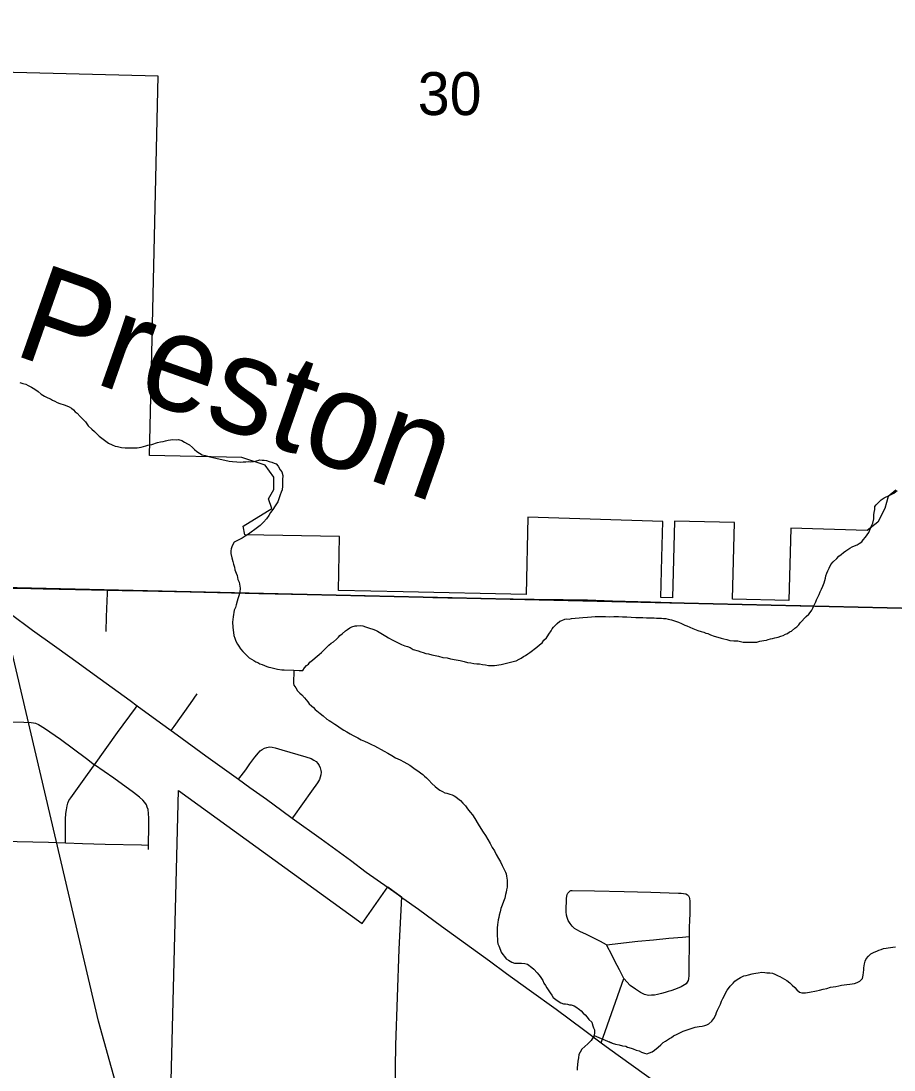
# Model space of a CAD drawing. Extents: x 0 to 34, y 0 to 22.
# Drawn here: x 7.471 to 8.323, y 16.904 to 17.928 of the extents above; entities that cross this region are included whole.
import ezdxf

# ---------------------------------------------------------------- set-up
doc = ezdxf.new("R2010")
doc.units = 0
for name, color, linetype in [('Default', 7, 'Continuous'), ('GM_X_City_Street', 7, 'Continuous'), ('GM_X_County_Road', 7, 'Continuous'), ('GM_X_Minor_River', 7, 'Continuous'), ('GM_X_Minor_River_Text', 7, 'Continuous'), ('GM_X_Rail_Line', 7, 'Continuous'), ('GM_X_Section', 7, 'Continuous'), ('GM_X_Section_Text', 7, 'Continuous')]:
    doc.layers.add(name, color=color, linetype=linetype)

msp = doc.modelspace()

# ---------------------------------------------------------------- linework, layer by layer
at = {"layer": 'Default'}
for points in [[(8.3248, 17.47), (8.3172, 17.4641), (8.3139, 17.4523), (8.3071, 17.4388), (8.2969, 17.4307), (8.2224, 17.4329), (8.2204, 17.3624), (8.1654, 17.3637), (8.1673, 17.4387), (8.1379, 17.4393), (8.1086, 17.44), (8.1067, 17.365), (8.0953, 17.3653), (8.0963, 17.4044), (8.0972, 17.4396), (7.9655, 17.4439), (7.9638, 17.3683), (7.8439, 17.3711), (7.7808, 17.3722), (7.7816, 17.4248), (7.6892, 17.4264), (7.6876, 17.4349), (7.7158, 17.4523), (7.7124, 17.4616), (7.7175, 17.4708), (7.7175, 17.4827), (7.709, 17.4945), (7.6863, 17.5021), (7.5961, 17.5038), (7.6046, 17.8742), (7.4249, 17.8786)], [(7.6168, 16.8685), (7.6244, 17.1771), (7.8038, 17.0472), (7.8289, 17.0831), (7.8424, 17.0734), (7.8398, 17.0223), (7.8365, 16.9285), (7.8354, 16.8636)]]:
    msp.add_lwpolyline(points, dxfattribs=at)
at = {"layer": 'GM_X_City_Street'}
for points in [[(7.5538, 17.3321), (7.5544, 17.3467), (7.5548, 17.3623), (7.5551, 17.3694), (7.5552, 17.3727)], [(7.6175, 17.2355), (7.6203, 17.2395), (7.6363, 17.262), (7.6427, 17.2713)], [(7.5141, 17.1261), (7.5141, 17.1318), (7.5143, 17.1492), (7.5146, 17.1547), (7.5152, 17.1583), (7.516, 17.1623), (7.5166, 17.1649), (7.5176, 17.1674), (7.5193, 17.17), (7.5293, 17.1837), (7.5358, 17.1928), (7.5426, 17.2022), (7.5651, 17.2337), (7.5825, 17.2575), (7.5842, 17.2598)], [(7.4575, 17.244), (7.4737, 17.2439), (7.4806, 17.2435), (7.4831, 17.2432), (7.4851, 17.2427), (7.488, 17.2414), (7.4939, 17.2378), (7.5093, 17.2272), (7.5348, 17.2083), (7.5426, 17.2022)], [(7.6832, 17.1881), (7.6858, 17.1914), (7.6904, 17.1973), (7.6943, 17.203), (7.699, 17.2096), (7.7025, 17.214), (7.7043, 17.2157), (7.7062, 17.2172), (7.7084, 17.2185), (7.7107, 17.2192), (7.7133, 17.2197), (7.7159, 17.2194), (7.7188, 17.2187), (7.7254, 17.2168), (7.7487, 17.2101), (7.754, 17.2082), (7.7568, 17.2067), (7.7588, 17.2053), (7.7605, 17.2035), (7.7619, 17.2014), (7.7629, 17.1991), (7.7636, 17.1967), (7.7638, 17.1949), (7.7636, 17.1924), (7.763, 17.19), (7.7621, 17.1877), (7.7602, 17.1845), (7.7543, 17.1764), (7.7367, 17.1517), (7.7355, 17.1502)], [(7.5953, 17.1194), (7.5953, 17.1238), (7.5955, 17.1422), (7.5955, 17.1501), (7.5953, 17.1548), (7.5948, 17.1585), (7.5941, 17.1609), (7.5932, 17.1632), (7.5918, 17.1653), (7.5898, 17.1677), (7.5866, 17.1706), (7.5807, 17.1752), (7.5615, 17.189), (7.5426, 17.2022)], [(7.4373, 17.1283), (7.4423, 17.1281), (7.4672, 17.1275), (7.4977, 17.1266), (7.5141, 17.1261), (7.5307, 17.1255), (7.5531, 17.1248), (7.5885, 17.124), (7.5953, 17.1238)], [(8.0373, 16.9309), (8.0594, 16.9936), (8.055, 17.0021), (8.0505, 17.0107), (8.0478, 17.0161), (8.0423, 17.0266), (8.0366, 17.0298), (8.0294, 17.0334), (8.0221, 17.0369), (8.0171, 17.0393), (8.0133, 17.0413), (8.0112, 17.0426), (8.0089, 17.0447), (8.007, 17.0472), (8.0051, 17.0504), (8.0039, 17.0532), (8.0032, 17.0556), (8.0029, 17.0586), (8.0029, 17.0635), (8.0032, 17.068), (8.0033, 17.0716), (8.0036, 17.074), (8.004, 17.0757), (8.0046, 17.0769), (8.0052, 17.0777), (8.006, 17.0784), (8.0068, 17.0791), (8.0077, 17.0795), (8.0087, 17.0796), (8.0308, 17.0793), (8.0596, 17.0785), (8.0855, 17.0778), (8.1125, 17.0771), (8.1152, 17.077), (8.1176, 17.0767), (8.1197, 17.0762), (8.1215, 17.0753), (8.1225, 17.0743), (8.1231, 17.0731), (8.1234, 17.0716), (8.1236, 17.0692), (8.1237, 17.065), (8.1236, 17.0566), (8.1235, 17.0508), (8.1232, 17.0431), (8.1231, 17.0379), (8.123, 17.0346), (8.1231, 17.03), (8.1229, 17.0226), (8.1228, 17.0108), (8.1228, 17.004), (8.1228, 16.9965), (8.1225, 16.9934), (8.122, 16.9916), (8.1212, 16.99), (8.12, 16.9886), (8.1185, 16.9874), (8.1152, 16.9856), (8.1098, 16.9832), (8.105, 16.9818), (8.1024, 16.981), (8.0996, 16.9801), (8.0961, 16.9792), (8.0923, 16.9781), (8.0893, 16.9775), (8.0863, 16.9773), (8.0832, 16.9772), (8.0794, 16.9781), (8.0757, 16.9801), (8.0707, 16.9833), (8.0655, 16.987), (8.0594, 16.9936)], [(8.0423, 17.0266), (8.0729, 17.0302), (8.0881, 17.0315), (8.1031, 17.033), (8.1167, 17.0341), (8.123, 17.0346)]]:
    msp.add_lwpolyline(points, dxfattribs=at)
at = {"layer": 'GM_X_County_Road'}
msp.add_line((8.0373, 16.9309), (8.0456, 16.9248), dxfattribs=at)
for points in [[(7.4258, 17.3747), (7.4379, 17.3658), (7.4602, 17.3499), (7.4821, 17.3335), (7.5034, 17.3184), (7.5186, 17.3076), (7.5301, 17.299), (7.5421, 17.2902), (7.5774, 17.2648), (7.5842, 17.2598)], [(7.4258, 17.3747), (7.4499, 17.3746), (7.4679, 17.3745), (7.4926, 17.374), (7.5552, 17.3727)], [(7.5552, 17.3727), (7.5648, 17.3725), (7.5695, 17.3724)], [(7.5695, 17.3724), (7.574, 17.3723), (7.6359, 17.371), (7.7031, 17.3694), (7.7664, 17.3679), (7.806, 17.367), (7.8447, 17.3664)], [(7.8447, 17.3664), (7.8727, 17.3655), (7.8876, 17.3651), (7.9062, 17.3648), (7.9196, 17.3646), (7.9512, 17.3641), (7.9716, 17.3637), (8.0002, 17.3634), (8.0239, 17.363), (8.0482, 17.3621), (8.0854, 17.3612), (8.1469, 17.3593), (8.232, 17.3575), (8.2793, 17.3563), (8.3331, 17.355), (8.3469, 17.3547)], [(7.5842, 17.2598), (7.6071, 17.2432), (7.6175, 17.2355)], [(7.6175, 17.2355), (7.6231, 17.2314), (7.6514, 17.2111), (7.6832, 17.1881)], [(7.6832, 17.1881), (7.6942, 17.1801), (7.7103, 17.1685), (7.7254, 17.1575), (7.7355, 17.1502)], [(7.7355, 17.1502), (7.7637, 17.1298), (7.7923, 17.109), (7.8079, 17.0976), (7.8292, 17.0825)], [(7.8292, 17.0825), (7.8394, 17.0752), (7.8427, 17.0728), (7.8435, 17.0722)], [(7.8435, 17.0722), (7.8588, 17.0612), (7.8813, 17.0446), (7.9283, 17.0108), (7.9449, 16.9987), (7.967, 16.9826), (7.9933, 16.9638), (8.0198, 16.9441), (8.0373, 16.9309)], [(8.0456, 16.9248), (8.0897, 16.8932), (8.1089, 16.8784), (8.1278, 16.8643), (8.1484, 16.8492), (8.1625, 16.839), (8.1776, 16.8281), (8.1938, 16.8163)]]:
    msp.add_lwpolyline(points, dxfattribs=at)
at = {"layer": 'GM_X_Minor_River'}
for points in [[(7.4696, 17.5751), (7.4726, 17.5743), (7.4756, 17.5734), (7.4778, 17.5722), (7.4812, 17.5706), (7.4842, 17.5686), (7.4875, 17.5663), (7.4905, 17.5639), (7.4939, 17.5619), (7.4969, 17.5603), (7.4995, 17.5591), (7.5017, 17.5579), (7.504, 17.557), (7.5062, 17.5558), (7.5088, 17.5546), (7.513, 17.5534), (7.5156, 17.5525), (7.5179, 17.5513), (7.5201, 17.5501), (7.522, 17.5485), (7.5238, 17.5466), (7.5257, 17.5454), (7.5286, 17.5419), (7.5312, 17.5395), (7.5338, 17.5368), (7.5363, 17.5329), (7.54, 17.5298), (7.5426, 17.5274), (7.5448, 17.5251), (7.547, 17.5227), (7.5563, 17.516), (7.5597, 17.5144), (7.5627, 17.5131), (7.565, 17.5127), (7.5688, 17.5118), (7.5725, 17.5113), (7.5752, 17.5113), (7.5779, 17.5116), (7.5809, 17.5115), (7.5843, 17.5114), (7.5862, 17.5117), (7.5881, 17.512), (7.5904, 17.5127), (7.5927, 17.5134), (7.5947, 17.5141), (7.5985, 17.5148), (7.6042, 17.5165), (7.6069, 17.5172)], [(7.6069, 17.5172), (7.6096, 17.5175), (7.6119, 17.5182), (7.6145, 17.5189), (7.6191, 17.5195), (7.6222, 17.5194), (7.6244, 17.5197), (7.6278, 17.5185), (7.6304, 17.5169), (7.6334, 17.5153), (7.6353, 17.5145), (7.6383, 17.5117), (7.6401, 17.5098), (7.6423, 17.5078), (7.6449, 17.5062), (7.6476, 17.5046), (7.6506, 17.5041), (7.6528, 17.5033), (7.6551, 17.5025), (7.6581, 17.502), (7.6611, 17.5015), (7.674, 17.4985), (7.6774, 17.498), (7.6815, 17.4979), (7.685, 17.4974), (7.6876, 17.4977), (7.6903, 17.4977), (7.6933, 17.498), (7.6952, 17.4979), (7.6979, 17.4982), (7.6998, 17.4985), (7.704, 17.4996), (7.7063, 17.4995), (7.7082, 17.4994), (7.7104, 17.499), (7.7131, 17.4982), (7.7157, 17.4973), (7.718, 17.4965), (7.7198, 17.4957), (7.7217, 17.4937), (7.7239, 17.4899), (7.7253, 17.4879), (7.7264, 17.4845), (7.7262, 17.4803), (7.7262, 17.4776), (7.7261, 17.4742), (7.7256, 17.4704), (7.7247, 17.4682), (7.7239, 17.4655), (7.7227, 17.4625), (7.7214, 17.4587), (7.719, 17.455), (7.7167, 17.4513), (7.7143, 17.4483), (7.7127, 17.4453), (7.7103, 17.4423), (7.7076, 17.439), (7.7044, 17.4357), (7.699, 17.4316), (7.6955, 17.4291), (7.6928, 17.4273), (7.6897, 17.4251), (7.6866, 17.4233), (7.6789, 17.4193), (7.6769, 17.4159), (7.676, 17.4129), (7.6756, 17.411), (7.6755, 17.4084), (7.6766, 17.4041), (7.6776, 17.4007), (7.6783, 17.398), (7.6793, 17.3949), (7.6796, 17.3923), (7.6807, 17.3892), (7.6817, 17.3869), (7.6824, 17.3831), (7.6838, 17.3804), (7.6842, 17.3785), (7.6848, 17.3746), (7.6843, 17.3705), (7.6835, 17.3671), (7.6826, 17.3641), (7.6818, 17.3618), (7.6809, 17.3584), (7.6801, 17.3558), (7.6789, 17.3531), (7.6779, 17.3467), (7.6774, 17.3414), (7.6776, 17.3364), (7.6785, 17.3284), (7.6796, 17.3257), (7.6806, 17.3227), (7.6821, 17.32), (7.6835, 17.318), (7.685, 17.3153), (7.6872, 17.3126), (7.6913, 17.3087), (7.6935, 17.3067), (7.6957, 17.3051), (7.698, 17.3039), (7.7002, 17.3027)], [(8.2547, 17.3798), (8.2555, 17.3821), (8.256, 17.3844), (8.2564, 17.3866), (8.2573, 17.3893), (8.2585, 17.3915), (8.2597, 17.3941), (8.2613, 17.3975), (8.2637, 17.4001), (8.2672, 17.4034), (8.2691, 17.4056), (8.2715, 17.4075), (8.2738, 17.4093), (8.2761, 17.4111), (8.2781, 17.4122), (8.28, 17.4137), (8.2823, 17.4148), (8.2846, 17.4158), (8.2869, 17.4169), (8.2889, 17.418), (8.2916, 17.4198), (8.2928, 17.4217), (8.2951, 17.4243), (8.2983, 17.4288), (8.3011, 17.4355), (8.3024, 17.4381), (8.3032, 17.4423), (8.3034, 17.4461), (8.3038, 17.4484), (8.3043, 17.4514), (8.3043, 17.4541), (8.3055, 17.4559), (8.3083, 17.4585), (8.3106, 17.4607), (8.3133, 17.4625), (8.3153, 17.4636), (8.3179, 17.4647), (8.3203, 17.4658), (8.323, 17.4672), (8.3261, 17.4698)], [(7.9862, 17.3298), (7.9882, 17.3328), (7.9894, 17.3347), (7.9906, 17.3365), (7.9926, 17.3384), (7.9941, 17.3402), (7.9969, 17.3424), (7.9988, 17.3431), (8.0018, 17.3442), (8.0038, 17.3445), (8.006, 17.3444), (8.0083, 17.3448), (8.0118, 17.3454), (8.0156, 17.3457), (8.0194, 17.346), (8.0239, 17.3462), (8.0277, 17.3465), (8.0312, 17.3468), (8.0369, 17.347), (8.0414, 17.3468), (8.0456, 17.3467), (8.0494, 17.347), (8.054, 17.3469), (8.0581, 17.3467), (8.0623, 17.3466), (8.0665, 17.3461), (8.071, 17.346), (8.0744, 17.3459), (8.0779, 17.3458), (8.0813, 17.3457), (8.0839, 17.3456), (8.0862, 17.3455), (8.0889, 17.3455), (8.0911, 17.3454), (8.0938, 17.3453), (8.0961, 17.3453), (8.098, 17.3448), (8.1002, 17.3448), (8.1025, 17.3443), (8.1059, 17.3435), (8.1127, 17.3414), (8.1157, 17.3401), (8.1187, 17.3385), (8.1209, 17.3377), (8.1236, 17.3365), (8.1266, 17.3353), (8.1314, 17.3332), (8.1348, 17.3324), (8.1375, 17.3315), (8.1393, 17.3307), (8.1412, 17.3303), (8.1438, 17.3291), (8.1476, 17.3278), (8.151, 17.3266), (8.1544, 17.3257), (8.157, 17.3252), (8.1597, 17.3244), (8.1627, 17.3236), (8.1668, 17.3231), (8.1687, 17.323), (8.1706, 17.323), (8.1733, 17.3225), (8.1759, 17.322), (8.1786, 17.322), (8.1812, 17.3219), (8.1839, 17.3218), (8.1866, 17.3217), (8.1892, 17.322), (8.1919, 17.3227), (8.1961, 17.3234), (8.1984, 17.3237), (8.2003, 17.3244), (8.2026, 17.3251), (8.2045, 17.3254), (8.2068, 17.3261), (8.2099, 17.3268), (8.2126, 17.3278), (8.2149, 17.3285), (8.2172, 17.3296), (8.2191, 17.3303), (8.221, 17.3318), (8.2229, 17.3325), (8.2261, 17.3354), (8.228, 17.3369), (8.23, 17.3387), (8.2315, 17.3406), (8.2374, 17.3469), (8.2398, 17.3491), (8.2413, 17.3509), (8.2429, 17.3532), (8.2437, 17.3551), (8.2449, 17.3573), (8.2458, 17.3592), (8.2466, 17.3611), (8.2474, 17.3633), (8.2486, 17.3656), (8.2498, 17.3682), (8.251, 17.3708), (8.2522, 17.3734), (8.2535, 17.3764), (8.2547, 17.3798)], [(7.7002, 17.3027), (7.7021, 17.3019), (7.7039, 17.3007), (7.7062, 17.2999), (7.7084, 17.299), (7.7107, 17.2982), (7.7126, 17.2974), (7.7148, 17.297), (7.7213, 17.2956), (7.7254, 17.2948), (7.7277, 17.2947), (7.7372, 17.2944), (7.7425, 17.2943), (7.7459, 17.2942), (7.7475, 17.2968), (7.7495, 17.299), (7.7514, 17.3005), (7.7526, 17.3023), (7.7553, 17.3042), (7.758, 17.3067), (7.76, 17.3082), (7.7619, 17.3097), (7.7643, 17.3119), (7.7662, 17.3137), (7.7686, 17.3163), (7.7713, 17.3189), (7.7736, 17.3207), (7.776, 17.3222), (7.7787, 17.3248), (7.7807, 17.3266), (7.7822, 17.3285), (7.7842, 17.3299), (7.7877, 17.3329), (7.7896, 17.3343), (7.7919, 17.3358), (7.7939, 17.3369), (7.7969, 17.3379), (7.7988, 17.3379), (7.8023, 17.3382), (7.8045, 17.3377), (7.8072, 17.3369), (7.8109, 17.3356), (7.8143, 17.3344), (7.8169, 17.3336), (7.8188, 17.3327), (7.827, 17.3276), (7.8296, 17.326), (7.833, 17.324), (7.8364, 17.3224), (7.839, 17.3211), (7.8424, 17.3195), (7.8454, 17.3183), (7.848, 17.3175), (7.8506, 17.3166), (7.8536, 17.3146), (7.8585, 17.3133), (7.8612, 17.3125), (7.8634, 17.3117), (7.866, 17.3108), (7.8687, 17.3104), (7.8717, 17.3095), (7.8751, 17.3087), (7.8785, 17.3082), (7.8826, 17.3069), (7.8868, 17.3064), (7.8902, 17.3056), (7.8955, 17.3047), (7.8996, 17.3038), (7.9034, 17.3029), (7.9068, 17.3021), (7.9098, 17.3016), (7.9129, 17.3011), (7.9159, 17.3007), (7.9185, 17.3006), (7.9212, 17.3001), (7.9242, 17.2997), (7.9272, 17.2992), (7.9299, 17.2991), (7.9329, 17.299), (7.9352, 17.2993), (7.9371, 17.2997), (7.9394, 17.3), (7.9421, 17.3007), (7.9448, 17.3014), (7.9474, 17.302), (7.9501, 17.3027), (7.9524, 17.3034), (7.9543, 17.3037), (7.957, 17.3052), (7.959, 17.3063), (7.9613, 17.3077), (7.9632, 17.3088), (7.9655, 17.3103), (7.9675, 17.3117), (7.9745, 17.3168), (7.9768, 17.3191), (7.9795, 17.3213), (7.9811, 17.3239), (7.9838, 17.3261), (7.985, 17.3279), (7.9862, 17.3298)], [(7.7372, 17.2944), (7.7368, 17.2815), (7.7371, 17.28), (7.739, 17.2773), (7.7408, 17.2745), (7.743, 17.2722), (7.7448, 17.2706), (7.7474, 17.2675), (7.7507, 17.2636), (7.7522, 17.2617), (7.7544, 17.2597), (7.7563, 17.2581), (7.7581, 17.2562), (7.7611, 17.2534), (7.7629, 17.2522), (7.7659, 17.2499), (7.7692, 17.2467), (7.7715, 17.2455), (7.7733, 17.2443), (7.7752, 17.2431), (7.7771, 17.2419), (7.7789, 17.2407), (7.7812, 17.2392), (7.7834, 17.2376), (7.786, 17.236), (7.789, 17.2344), (7.792, 17.2324), (7.795, 17.2308), (7.7995, 17.2284), (7.8028, 17.2267), (7.8062, 17.2251), (7.8096, 17.2235), (7.8129, 17.2219), (7.8159, 17.2207), (7.8253, 17.2154), (7.829, 17.2134), (7.8328, 17.2114), (7.8365, 17.209), (7.841, 17.207), (7.8444, 17.205), (7.8473, 17.2034), (7.8503, 17.2018), (7.8529, 17.1998), (7.8555, 17.1978), (7.8582, 17.1963), (7.8608, 17.1943), (7.863, 17.1927), (7.8648, 17.1911), (7.8667, 17.1895), (7.8689, 17.1872), (7.8719, 17.1841), (7.8752, 17.1809), (7.877, 17.1794), (7.8796, 17.1774), (7.8823, 17.1762), (7.8845, 17.175), (7.8864, 17.1745), (7.8894, 17.1737), (7.8917, 17.1728), (7.8935, 17.172), (7.8954, 17.1708), (7.8973, 17.1693), (7.8999, 17.1673), (7.9021, 17.1646), (7.9046, 17.1622), (7.9068, 17.1591), (7.9094, 17.156), (7.9116, 17.1533), (7.9138, 17.1498), (7.917, 17.1444), (7.9196, 17.1401), (7.9221, 17.1366), (7.9243, 17.1331), (7.9265, 17.1293), (7.9287, 17.1254), (7.9308, 17.1215), (7.933, 17.1184), (7.9348, 17.1146), (7.937, 17.1107), (7.9388, 17.1076), (7.9406, 17.1041), (7.9438, 17.0976), (7.9445, 17.0957), (7.9448, 17.0934), (7.9451, 17.0915), (7.9455, 17.0895), (7.9454, 17.0873), (7.9453, 17.085), (7.9453, 17.0827), (7.9448, 17.0801), (7.9444, 17.0778), (7.9439, 17.0755), (7.9431, 17.0721), (7.9418, 17.0687), (7.9406, 17.0654), (7.9393, 17.062), (7.9385, 17.0589), (7.9376, 17.0556), (7.9372, 17.0533), (7.9367, 17.051), (7.9363, 17.0484)], [(7.9363, 17.0484), (7.9359, 17.0465), (7.9357, 17.0427), (7.9357, 17.04), (7.9356, 17.0377), (7.9355, 17.0351), (7.9358, 17.0324), (7.9361, 17.0297), (7.9364, 17.0275), (7.9371, 17.0255), (7.9389, 17.0213), (7.9396, 17.0194), (7.9411, 17.0171), (7.9429, 17.0151), (7.9444, 17.0128), (7.9466, 17.0116), (7.95, 17.0096), (7.9526, 17.0087), (7.9553, 17.0087), (7.9575, 17.0086), (7.9594, 17.0085), (7.9625, 17.0084), (7.9651, 17.0076), (7.9696, 17.0044), (7.9714, 17.0029), (7.9748, 16.9993), (7.9762, 16.9974), (7.9777, 16.9955), (7.9802, 16.9916), (7.9813, 16.9893), (7.9827, 16.9869), (7.9842, 16.9846), (7.9853, 16.9827), (7.9875, 16.9796), (7.9889, 16.9773), (7.9904, 16.9753), (7.993, 16.9733), (7.996, 16.971), (7.9978, 16.9698), (8.0005, 16.9689), (8.0024, 16.9689), (8.0042, 16.9685), (8.0061, 16.968), (8.008, 16.968), (8.0107, 16.9671), (8.0125, 16.9659), (8.0159, 16.9636), (8.0177, 16.962), (8.0196, 16.96), (8.0214, 16.9581), (8.0236, 16.9561), (8.0251, 16.9538), (8.028, 16.951), (8.0291, 16.9476), (8.0298, 16.9457), (8.0305, 16.9437), (8.0308, 16.9411), (8.0303, 16.938), (8.0275, 16.9332), (8.024, 16.9299), (8.0213, 16.9273), (8.0182, 16.9247), (8.0166, 16.9217), (8.0154, 16.9195), (8.0149, 16.9164), (8.0144, 16.913), (8.0139, 16.9096), (8.0138, 16.9066), (8.0138, 16.9043)], [(8.293, 16.997), (8.2931, 16.9996), (8.2935, 17.0023), (8.2936, 17.0042), (8.294, 17.0061), (8.2941, 17.008), (8.2949, 17.0106), (8.2957, 17.0129), (8.2981, 17.0155), (8.3004, 17.0177), (8.3035, 17.0195), (8.3062, 17.0205), (8.3081, 17.0213), (8.3104, 17.0219), (8.3127, 17.023), (8.3154, 17.0233), (8.3173, 17.0236), (8.3196, 17.024), (8.3219, 17.0243), (8.3245, 17.0246)], [(8.0303, 16.938), (8.048, 16.9307), (8.045, 16.9319), (8.048, 16.9307), (8.0513, 16.9295), (8.0548, 16.929), (8.0581, 16.9281), (8.0612, 16.9276), (8.063, 16.9268), (8.0664, 16.9256), (8.0683, 16.9252), (8.0713, 16.9239), (8.0743, 16.9231), (8.0766, 16.9219), (8.0796, 16.921), (8.0818, 16.9202), (8.0868, 16.9223), (8.0892, 16.9238), (8.0927, 16.9267), (8.0954, 16.9289), (8.0977, 16.9312), (8.1001, 16.9326), (8.102, 16.9337), (8.1039, 16.9352), (8.1059, 16.9362), (8.1078, 16.9377), (8.1113, 16.9395), (8.1132, 16.9402), (8.1151, 16.9413), (8.1171, 16.9424), (8.1201, 16.9434), (8.122, 16.9441), (8.124, 16.9445), (8.1259, 16.9452), (8.1289, 16.9462), (8.1308, 16.9465), (8.1328, 16.9469), (8.1358, 16.9472), (8.1385, 16.9478), (8.1404, 16.9485), (8.1423, 16.9496), (8.1451, 16.9522), (8.147, 16.9548), (8.149, 16.9582), (8.1499, 16.9604), (8.1507, 16.9627), (8.1519, 16.9653), (8.1535, 16.9687), (8.1547, 16.9717), (8.156, 16.9743), (8.16, 16.9822), (8.1616, 16.9841), (8.1631, 16.9863), (8.1659, 16.9893), (8.1675, 16.9911), (8.1698, 16.9926), (8.1733, 16.9947), (8.1764, 16.9962), (8.1786, 16.9965), (8.1809, 16.9972), (8.1844, 16.9982), (8.1863, 16.9985), (8.1882, 16.9989), (8.1905, 16.9992), (8.1939, 16.9999), (8.197, 16.9994), (8.1989, 16.9993), (8.2019, 16.9992), (8.2045, 16.9988), (8.2068, 16.998), (8.2098, 16.9963), (8.2117, 16.9955), (8.2139, 16.9943), (8.2161, 16.9931), (8.2184, 16.9919), (8.2214, 16.9895), (8.2236, 16.9872), (8.2262, 16.9848), (8.228, 16.9825), (8.2306, 16.9805), (8.2332, 16.9797), (8.2366, 16.9796), (8.2386, 16.9799), (8.2405, 16.9803), (8.2473, 16.9816), (8.2504, 16.9822), (8.2538, 16.9833), (8.2573, 16.9839), (8.2611, 16.9854), (8.2661, 16.986), (8.2691, 16.9866), (8.2718, 16.9873), (8.2745, 16.9876), (8.2771, 16.9879), (8.2798, 16.9882), (8.2821, 16.9885), (8.2844, 16.9889), (8.2871, 16.9899), (8.2898, 16.991), (8.2921, 16.9936), (8.293, 16.997)]]:
    msp.add_lwpolyline(points, dxfattribs=at)
at = {"layer": 'GM_X_Rail_Line'}
msp.add_lwpolyline([(8.3191, 14.1), (8.2652, 14.2915), (7.9984, 15.3006), (7.7787, 16.1186), (7.5464, 16.952), (7.4475, 17.3725), (7.3986, 17.4999), (7.3389, 17.6382), (7.2697, 17.7778), (7.0716, 18.0894), (7.0417, 18.1342), (7.0105, 18.1626), (6.978, 18.1748), (6.9427, 18.181)], dxfattribs=at)
at = {"layer": 'GM_X_Section'}
for points in [[(7.436, 18.3837), (8.3692, 18.3604), (8.3445, 17.3547), (7.4101, 17.3762)], [(7.4101, 17.3762), (8.3445, 17.3547), (8.3472, 17.3547), (8.327, 16.3478), (7.3849, 16.3697)]]:
    msp.add_lwpolyline(points, close=True, dxfattribs=at)

# ---------------------------------------------------------------- texts
at = {"layer": 'GM_X_Minor_River_Text'}
msp.add_text('Preston', height=0.09475, rotation=340.6161, dxfattribs=at).set_placement((7.4612, 17.6031))
at = {"layer": 'GM_X_Section_Text'}
msp.add_text('30', height=0.04186, rotation=0, dxfattribs=at).set_placement((7.8581, 17.8361))

doc.saveas('drawing.dxf')
